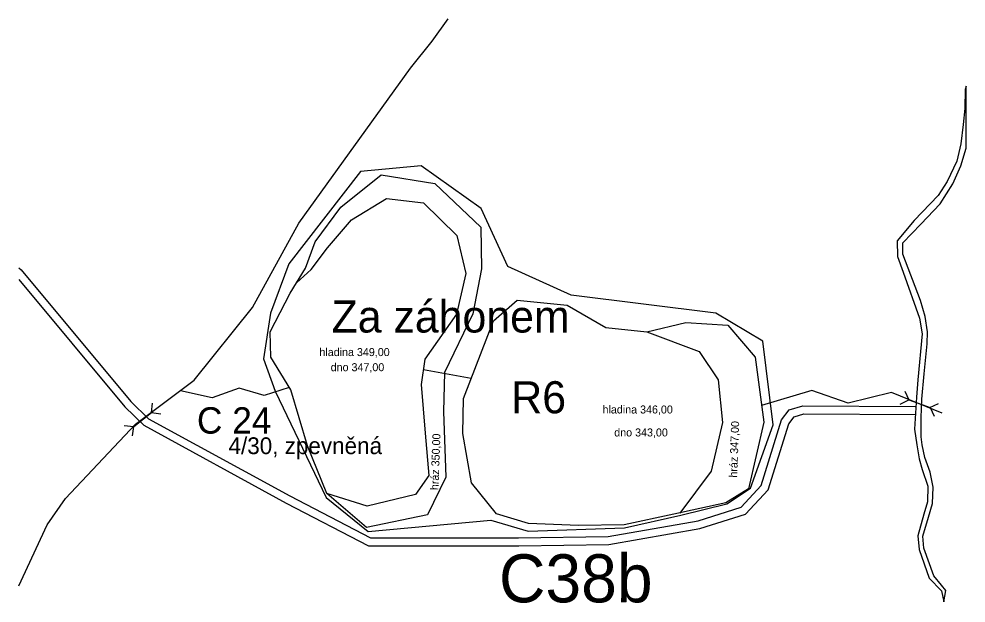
# Model space of a CAD drawing. Extents: x -552149 to -551557, y -1037581 to -1037216.
import ezdxf

# ---------------------------------------------------------------- set-up
doc = ezdxf.new("R2010")
doc.units = 0
for name, color, linetype in [('cesty', 7, 'Continuous'), ('Vrstva 10', 7, 'Continuous'), ('Vrstva 25', 7, 'Continuous'), ('Vrstva 34', 7, 'Continuous'), ('Vrstva 37', 7, 'Continuous'), ('Vrstva 38', 7, 'Continuous'), ('Vrstva 5', 7, 'Continuous')]:
    doc.layers.add(name, color=color, linetype=linetype)

msp = doc.modelspace()

# ---------------------------------------------------------------- linework, layer by layer
at = {"layer": 'cesty'}
for p, q in [((-551595.59, -1037448.55), (-551593.04, -1037453.92)), ((-552065.95, -1037461.84), (-552065.23, -1037455.95)), ((-551598.4, -1037456.47), (-551593.04, -1037453.92)), ((-551593.04, -1037453.92), (-551579.79, -1037458.62)), ((-551579.8, -1037458.61), (-551574.44, -1037456.06)), ((-551579.79, -1037458.62), (-551577.24, -1037463.98)), ((-552077.01, -1037470.51), (-552065.94, -1037461.84)), ((-552065.94, -1037461.84), (-552060.05, -1037462.56)), ((-552082.91, -1037469.79), (-552077.01, -1037470.5)), ((-552077.73, -1037476.4), (-552077.01, -1037470.51))]:
    msp.add_line(p, q, dxfattribs=at)
for points in [[(-552148.71, -1037371.4), (-552147.31, -1037372.7), (-552078.81, -1037454.84), (-552067.76, -1037465.67), (-551979.49, -1037513.89), (-551929.23, -1037540.07), (-551836.69, -1037540.07), (-551780.76, -1037539.14), (-551724.62, -1037529.31), (-551697.77, -1037520.8), (-551685.23, -1037507.43), (-551672.52, -1037466.44), (-551667.67, -1037460.2), (-551659.26, -1037457.62), (-551589.08, -1037457.94)], [(-552148.71, -1037378.83), (-552082.49, -1037458.24), (-552070.76, -1037469.73), (-551981.84, -1037518.3), (-551930.45, -1037545.07), (-551836.65, -1037545.07), (-551780.28, -1037544.13), (-551723.43, -1037534.18), (-551695.01, -1037525.17), (-551680.8, -1037510.01), (-551668.01, -1037468.79), (-551664.69, -1037464.52), (-551658.53, -1037462.63), (-551588.93, -1037463.11)]]:
    msp.add_lwpolyline(points, dxfattribs=at)
at = {"layer": 'Vrstva 10'}
msp.add_lwpolyline([(-552148.71, -1037570.07), (-552131.12, -1037531.81), (-552119.55, -1037515.47), (-552075.88, -1037469), (-552039.3, -1037441.57), (-552002.86, -1037396.17), (-551973.94, -1037343.53), (-551904.18, -1037246.81), (-551890.72, -1037229.87), (-551880.68, -1037216.1)], dxfattribs=at)
at = {"layer": 'Vrstva 25'}
msp.add_lwpolyline([(-551956.9, -1037514.78), (-551930.71, -1037535.95), (-551853.98, -1037529.06), (-551830.69, -1037535.94), (-551770.63, -1037533.83), (-551735.44, -1037525.89), (-551706.6, -1037518.74), (-551691.79, -1037508.96), (-551677.76, -1037469.53), (-551684.11, -1037417.14), (-551713.48, -1037399.68), (-551803.97, -1037388.57), (-551843.39, -1037370.58), (-551860.06, -1037334.33), (-551897.63, -1037307.87), (-551935.47, -1037311.31), (-551980.18, -1037368.99), (-551991.56, -1037399.83), (-551996.06, -1037428.26), (-551988.65, -1037448.37)], close=True, dxfattribs=at)
for points in [[(-551947.68, -1037333.68), (-551922.43, -1037313.32), (-551889.08, -1037318.91), (-551860.31, -1037346.04), (-551859.89, -1037372.15), (-551865.19, -1037400.14), (-551883.07, -1037436.86), (-551883.56, -1037461.16), (-551882.14, -1037502.04), (-551893.51, -1037525.63), (-551931.59, -1037533.59), (-551956.39, -1037512.36), (-551968.48, -1037482.64), (-551978.96, -1037447.62), (-551991.47, -1037427.19), (-551991.79, -1037411.51), (-551979.34, -1037387.23), (-551969.68, -1037371.66), (-551963.63, -1037355.18), (-551947.68, -1037333.68)], [(-551975.32, -1037380.75), (-551966.18, -1037372.51), (-551956.12, -1037359), (-551941.02, -1037341.52), (-551919.15, -1037328.18), (-551896.18, -1037330.9), (-551875.28, -1037351.34), (-551869.74, -1037375), (-551875.46, -1037400.35), (-551895.15, -1037428.48), (-551897.48, -1037444.25), (-551895.14, -1037474.73), (-551892.78, -1037501.12), (-551901.12, -1037512.87), (-551931.18, -1037520.26), (-551956.39, -1037512.36)], [(-551837.6, -1037391.68), (-551806.41, -1037394.72), (-551782.19, -1037408.67), (-551756.52, -1037411.4), (-551732.21, -1037405.55), (-551706.01, -1037407.29), (-551688.94, -1037427.15), (-551683.59, -1037467.79), (-551693.18, -1037509.49), (-551707.36, -1037518.17), (-551739.7, -1037525.3), (-551770.77, -1037531.8), (-551799.31, -1037532.4), (-551830.54, -1037531.07), (-551850.48, -1037524.95), (-551866.09, -1037505.62), (-551871.5, -1037474.98), (-551871.14, -1037452.99), (-551852.3, -1037404.59), (-551837.6, -1037391.68)], [(-551756.52, -1037411.4), (-551724.04, -1037423.74), (-551712.09, -1037441.47), (-551709.34, -1037468.06), (-551716.53, -1037498.46), (-551736.1, -1037524.51)]]:
    msp.add_lwpolyline(points, dxfattribs=at)
at = {"layer": 'Vrstva 38'}
for p, q in [((-551557.88, -1037260.2), (-551558.05, -1037272.09)), ((-551557.28, -1037258.04), (-551557.88, -1037260.2)), ((-551557.28, -1037296.71), (-551557.28, -1037258.04)), ((-551558.05, -1037272.09), (-551558.98, -1037282.06)), ((-551558.98, -1037282.06), (-551560.51, -1037293.99)), ((-551560.51, -1037293.99), (-551563.12, -1037304.98)), ((-551560.5, -1037307.88), (-551557.28, -1037296.71)), ((-551563.12, -1037304.98), (-551569.1, -1037317.59)), ((-551565.59, -1037318.95), (-551560.5, -1037307.88)), ((-551569.1, -1037317.59), (-551574.68, -1037326.35)), ((-551573.46, -1037331.57), (-551565.59, -1037318.95)), ((-551574.68, -1037326.35), (-551589.67, -1037341.96)), ((-551585.5, -1037344.23), (-551573.46, -1037331.57)), ((-551589.67, -1037341.96), (-551600.21, -1037354.68)), ((-551596.83, -1037355.81), (-551585.5, -1037344.23)), ((-551600.21, -1037354.68), (-551600.01, -1037364.38)), ((-551596.74, -1037363.01), (-551596.83, -1037355.81)), ((-551585.8, -1037391.91), (-551596.74, -1037363.01)), ((-551600.01, -1037364.38), (-551596.55, -1037374.13)), ((-551596.55, -1037374.13), (-551586.41, -1037402.87)), ((-551582.88, -1037401.79), (-551585.8, -1037391.91)), ((-551586.41, -1037402.87), (-551584.78, -1037412.74)), ((-551581.42, -1037411.32), (-551582.88, -1037401.79)), ((-551581.53, -1037418.85), (-551581.42, -1037411.32)), ((-551584.78, -1037412.74), (-551587.46, -1037441.42)), ((-551583.45, -1037437.67), (-551581.53, -1037418.85)), ((-551584.87, -1037453.46), (-551583.45, -1037437.67)), ((-551587.46, -1037441.42), (-551588.3, -1037452.11)), ((-551588.3, -1037452.11), (-551589.4, -1037472.22)), ((-551585.41, -1037465.08), (-551584.87, -1037453.46)), ((-551585.4, -1037476.88), (-551585.41, -1037465.08)), ((-551589.4, -1037472.22), (-551588.03, -1037481.93)), ((-551588.03, -1037481.93), (-551586.5, -1037490.77)), ((-551584.67, -1037481.91), (-551585.4, -1037476.88)), ((-551583.04, -1037489.78), (-551584.67, -1037481.91)), ((-551586.5, -1037490.77), (-551584.71, -1037497.36)), ((-551579.73, -1037499.04), (-551583.04, -1037489.78)), ((-551584.71, -1037497.36), (-551581.18, -1037507.74)), ((-551577.78, -1037508.45), (-551579.73, -1037499.04)), ((-551581.18, -1037507.74), (-551581.34, -1037517.61)), ((-551578.17, -1037518.49), (-551577.78, -1037508.45)), ((-551581.34, -1037517.61), (-551583.73, -1037525.21)), ((-551580.63, -1037527.18), (-551578.17, -1037518.49)), ((-551583.73, -1037525.21), (-551587.41, -1037538.68)), ((-551584.17, -1037538.91), (-551580.63, -1037527.18)), ((-551587.41, -1037538.68), (-551586.59, -1037547.32)), ((-551583.7, -1037546.51), (-551584.17, -1037538.91)), ((-551586.59, -1037547.32), (-551580.29, -1037565.24)), ((-551577.31, -1037563.79), (-551583.7, -1037546.51)), ((-551580.29, -1037565.24), (-551572.58, -1037573.05)), ((-551572.57, -1037569.62), (-551577.31, -1037563.79)), ((-551569.99, -1037572.81), (-551572.57, -1037569.62)), ((-551572.58, -1037573.05), (-551571.26, -1037579.98)), ((-551571.26, -1037579.98), (-551569.99, -1037572.81))]:
    msp.add_line(p, q, dxfattribs=at)
at = {"layer": 'Vrstva 5'}
for points in [[(-551866.3, -1037440.55), (-551866.3, -1037440.55), (-551866.3, -1037440.55), (-551866.3, -1037440.55), (-551896.12, -1037435.04)], [(-551979.88, -1037446.11), (-551995.59, -1037451.24), (-552011.15, -1037446.61), (-552028.08, -1037452.54), (-552047.81, -1037448.17)], [(-551572.19, -1037462.2), (-551603.84, -1037449.21), (-551630.8, -1037456.02), (-551653.62, -1037448.06), (-551684.96, -1037457.41)]]:
    msp.add_lwpolyline(points, dxfattribs=at)

# ---------------------------------------------------------------- texts
at = {"layer": 'cesty'}
for s, height, p in [('C 24', 16.481, (-552037.56, -1037474.96)), ('4/30, zpevněná', 10.4807, (-552017.82, -1037487.75))]:
    msp.add_text(s, height=height, dxfattribs=at).set_placement(p)
at = {"layer": 'Vrstva 10'}
for s, height, p in [('hladina 349,00', 5, (-551961.07, -1037426.55)), ('dno 347,00', 5, (-551954.04, -1037436)), ('R6', 20, (-551841.25, -1037462.26)), ('hladina 346,00', 5, (-551784.26, -1037462.39)), ('dno 343,00', 5, (-551776.96, -1037476.72))]:
    msp.add_text(s, height=height, dxfattribs=at).set_placement(p)
for s, p in [('hráz 347,00', (-551700.24, -1037502.49)), ('hráz 350,00', (-551886.77, -1037510.3))]:
    msp.add_text(s, height=5, rotation=87.87594, dxfattribs=at).set_placement(p)
at = {"layer": 'Vrstva 34'}
msp.add_text('Za záhonem', height=20, dxfattribs=at).set_placement((-551953.48, -1037411.85))
at = {"layer": 'Vrstva 37'}
msp.add_text('C38b', height=30, dxfattribs=at).set_placement((-551848.93, -1037580.29))

doc.saveas('drawing.dxf')
